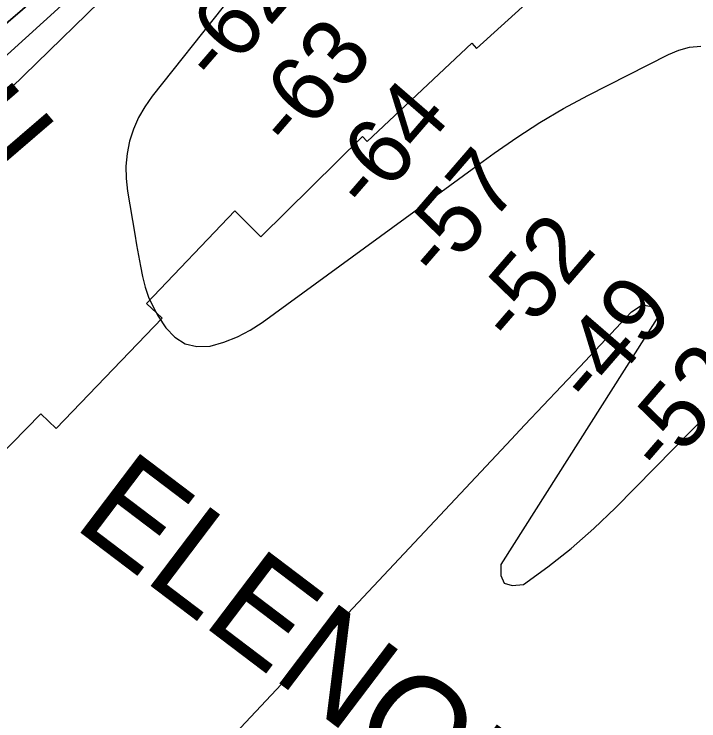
# Model space of a CAD drawing. Extents: x 3324104 to 3361979, y 612876 to 638273.
# Drawn here: x 3335643 to 3336336, y 623340 to 624056 of the extents above; entities that cross this region are included whole.
import ezdxf

# ---------------------------------------------------------------- set-up
doc = ezdxf.new("R2010")
doc.units = 0
for name, color, linetype in [('V-CHAN-NAID', 7, 'Continuous'), ('V-RIVR-EDGE', 7, 'Continuous'), ('V-RIVR-RANG', 7, 'Continuous'), ('V-RRAP-RVMT', 7, 'Continuous'), ('V-RRAP-RVMT-IDEN', 7, 'Continuous'), ('V-TOPO-DPTH', 7, 'Continuous'), ('V-TOPO-GNAM-IDEN', 7, 'Continuous'), ('V-TOPO-MAJR', 7, 'Continuous'), ('V-TOPO-MINR', 7, 'Continuous')]:
    doc.layers.add(name, color=color, linetype=linetype)

msp = doc.modelspace()

# ---------------------------------------------------------------- linework, layer by layer
at = {"layer": 'V-RIVR-EDGE'}
msp.add_spline([(3335831.32, 624380.07), (3335822.52, 624366.93), (3335812.6, 624347.94), (3335803.8, 624337), (3335798.3, 624329.34), (3335794.25, 624318.01), (3335789.11, 624311.45), (3335780.69, 624303.06), (3335767.12, 624285.18), (3335747.68, 624260.74), (3335731.91, 624240.67), (3335698.21, 624211.15), (3335677.33, 624192.19), (3335662.67, 624176.51), (3335646.54, 624160.83), (3335632.25, 624145.88), (3335615.76, 624131.3), (3335603.31, 624119.99), (3335592.31, 624106.86), (3335584.97, 624096.64), (3335578.75, 624094.47), (3335568.5, 624087.91), (3335560.08, 624080.99), (3335551.64, 624071.14), (3335543.59, 624065.31), (3335538.1, 624063.5), (3335532.97, 624059.12), (3335530.77, 624053.64), (3335527.83, 624050.73), (3335522.71, 624050.01), (3335516.13, 624049.66), (3335512.48, 624049.3), (3335497.46, 624037.64), (3335485.38, 624029.26), (3335478.43, 624027.09), (3335472.93, 624023.81), (3335468.54, 624020.53), (3335461.22, 624015.07), (3335455, 624014.35), (3335451.71, 624013.63), (3335449.51, 624010.71), (3335449.5, 624008.15), (3335450.23, 624006.32), (3335449.12, 624003.03), (3335446.93, 624002.31), (3335438.15, 624001.6), (3335427.54, 623996.87), (3335420.22, 623992.87), (3335409.6, 623985.22), (3335401.9, 623977.93), (3335392.74, 623968.45), (3335375.53, 623956.06), (3335352.83, 623941.86), (3335330.87, 623930.22), (3335312.58, 623925.88), (3335303.44, 623923.7), (3335298.32, 623921.52), (3335294.28, 623916.42), (3335290.62, 623913.87), (3335277.45, 623909.88), (3335265.37, 623904.42), (3335244.14, 623893.51), (3335232.43, 623886.59), (3335209, 623874.22), (3335181.91, 623858.57), (3335164.71, 623847.28), (3335147.86, 623833.07), (3335126.96, 623810.46), (3335107.18, 623791.5), (3335089.59, 623775.46), (3335052.95, 623741.55), (3335041.96, 623729.51), (3335028.75, 623711.27), (3335018.12, 623697.77), (3335015.55, 623695.58), (3335013.36, 623695.22), (3335008.97, 623694.14), (3335004.57, 623690.49), (3334995.77, 623678.45), (3334991.73, 623671.88), (3334991.35, 623666.03), (3334990.6, 623658.36), (3334993.51, 623650.67), (3334993.87, 623647.75), (3334996.41, 623642.63), (3334993.11, 623636.79), (3334983.57, 623621.46), (3334967.07, 623601.76), (3334950.94, 623584.98), (3334928.97, 623567.85)], degree=3, dxfattribs=at)
at = {"layer": 'V-RRAP-RVMT'}
for p, q in [((3336110.87, 624020.96), (3336216.28, 624116.69)), ((3336000.27, 623926.63), (3336106.15, 624026.1)), ((3336106.15, 624026.1), (3336110.87, 624020.96)), ((3335892.45, 623830.17), (3335995.36, 623931.78)), ((3335995.36, 623931.78), (3336000.27, 623926.63)), ((3335776.57, 623762.81), (3335866.17, 623856.4)), ((3335866.17, 623856.4), (3335892.45, 623830.17)), ((3335792.39, 623747.68), (3335776.57, 623762.81)), ((3335685.34, 623636.1), (3335792.39, 623747.68)), ((3335568.01, 623547.52), (3335669.85, 623651)), ((3335669.85, 623651), (3335685.34, 623636.1))]:
    msp.add_line(p, q, dxfattribs=at)
at = {"layer": 'V-TOPO-DPTH'}
for points in [[(3334876.37, 623307.56), (3334930.19, 623373.62), (3334985.07, 623438.8), (3335040.66, 623503.4), (3335142.54, 623619.88), (3335147.8, 623625.73), (3335153.15, 623631.48), (3335158.65, 623637.09), (3335766.96, 624160.22), (3335786.82, 624179.28), (3336309.04, 624623.27)], [(3334876.37, 623307.56), (3334930.19, 623373.62), (3334985.07, 623438.8), (3335040.66, 623503.4), (3335142.54, 623619.88), (3335147.8, 623625.73), (3335153.15, 623631.48), (3335158.65, 623637.09), (3335766.96, 624160.22), (3335786.82, 624179.28), (3336309.04, 624623.27)], [(3336333.29, 624602.03), (3335901.82, 624256.4), (3335883.92, 624241.91), (3335866.32, 624227.07), (3335849.18, 624211.7), (3335832.35, 624195.97), (3335823.69, 624187.62), (3335802.73, 624167.48), (3335781.74, 624147.37), (3335154.43, 623578.18), (3335126.82, 623550.99), (3335120.47, 623544.56), (3335090.54, 623513.32), (3335061.26, 623481.5), (3335032.97, 623448.8), (3335005.33, 623415.52), (3334637.16, 622958.19)], [(3336333.29, 624602.03), (3335901.82, 624256.4), (3335883.92, 624241.91), (3335866.32, 624227.07), (3335849.18, 624211.7), (3335832.35, 624195.97), (3335823.69, 624187.62), (3335802.73, 624167.48), (3335781.74, 624147.37), (3335154.43, 623578.18), (3335126.82, 623550.99), (3335120.47, 623544.56), (3335090.54, 623513.32), (3335061.26, 623481.5), (3335032.97, 623448.8), (3335005.33, 623415.52), (3334637.16, 622958.19)]]:
    msp.add_lwpolyline(points, dxfattribs=at)
at = {"layer": 'V-TOPO-MAJR'}
for points in [[(3335792.79, 624130.39), (3335409.69, 623757.6)], [(3335711.35, 623162.02), (3336141.14, 623619.97), (3336159.66, 623639.68), (3336178.21, 623659.37), (3336196.79, 623679.02), (3336215.38, 623698.66), (3336267.84, 623754.23), (3336278.55, 623761.33), (3336288.34, 623759.52), (3336293.66, 623747.92), (3336135.3, 623498.62), (3336135.57, 623487.32), (3336138.97, 623479.58), (3336147.08, 623477.18), (3336158.32, 623478.34), (3336182.96, 623496.06), (3336206.81, 623514.71), (3336229.51, 623534.76), (3336251.43, 623555.73), (3336330.57, 623636.14), (3336339.55, 623645.33)]]:
    msp.add_lwpolyline(points, dxfattribs=at)
at = {"layer": 'V-TOPO-MINR'}
for points in [[(3336309.04, 624623.27), (3335786.82, 624179.28), (3335766.96, 624160.22), (3335158.65, 623637.09), (3335153.15, 623631.48), (3335147.8, 623625.73), (3335142.54, 623619.88), (3335040.66, 623503.4), (3334985.07, 623438.8), (3334930.19, 623373.62), (3334876.37, 623307.56)], [(3336333.29, 624602.03), (3335901.82, 624256.4), (3335883.92, 624241.91), (3335866.32, 624227.07), (3335849.18, 624211.7), (3335832.35, 624195.97), (3335823.69, 624187.62), (3335802.73, 624167.48), (3335781.74, 624147.37), (3335154.43, 623578.18), (3335126.82, 623550.99), (3335120.47, 623544.56), (3335090.54, 623513.32), (3335061.26, 623481.5), (3335032.97, 623448.8), (3335005.33, 623415.52), (3334637.16, 622958.19)], [(3335854.27, 624062.95), (3335782.4, 623972.38), (3335775.07, 623961.86), (3335768.66, 623950.86), (3335763.65, 623939.16), (3335759.58, 623927), (3335757.08, 623914.43), (3335755.68, 623901.81), (3335755.93, 623889.11), (3335757.28, 623876.37), (3335764.75, 623832.9), (3335766.64, 623822.12), (3335768.58, 623811.35), (3335770.59, 623800.59), (3335772.64, 623789.84), (3335775.32, 623779.33), (3335778.75, 623769.12), (3335783.31, 623759.37), (3335788.62, 623749.91), (3335796.21, 623738.07), (3335805.38, 623728.5), (3335815.71, 623721.76), (3335827.8, 623719.26), (3335841.04, 623719.58), (3335855.11, 623723.65), (3335868.67, 623728.8), (3335881.5, 623735.59), (3335893.84, 623743.46), (3336038.75, 623849.16), (3336061.27, 623865.6), (3336083.79, 623882.04), (3336106.29, 623898.5), (3336128.79, 623914.97), (3336151.64, 623930.87), (3336174.96, 623946.01), (3336198.98, 623960), (3336223.48, 623973.22), (3336305.19, 624014.81), (3336315.8, 624019.11), (3336326.64, 624022.15), (3336337.84, 624023.32)]]:
    msp.add_lwpolyline(points, dxfattribs=at)

# ---------------------------------------------------------------- texts
at = {"layer": 'V-CHAN-NAID'}
msp.add_text('BAYOU GOULA BEND "197" (196.2)', height=100, rotation=312.88214, dxfattribs=at).set_placement((3334946.23, 623573.42))
at = {"layer": 'V-RIVR-RANG'}
for s, p in [('-62', (3335848.79, 623981.85)), ('-63', (3335923.91, 623915.83)), ('-64', (3336001.61, 623852.8)), ('-57', (3336073.79, 623783.4)), ('-52', (3336149.25, 623717.78)), ('-49', (3336227.99, 623655.95)), ('-52', (3336300.17, 623586.54))]:
    msp.add_text(s, height=67, rotation=49.13256, dxfattribs=at).set_placement(p)
at = {"layer": 'V-RRAP-RVMT-IDEN'}
msp.add_text('WHITE', height=100, rotation=40.68145, dxfattribs=at).set_placement((3335360.26, 623670.19))
at = {"layer": 'V-TOPO-GNAM-IDEN'}
msp.add_text('ELENORA LDG.', height=99.9998, rotation=322.84863, dxfattribs=at).set_placement((3335700.98, 623537.3))

doc.saveas('drawing.dxf')
